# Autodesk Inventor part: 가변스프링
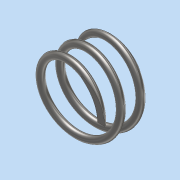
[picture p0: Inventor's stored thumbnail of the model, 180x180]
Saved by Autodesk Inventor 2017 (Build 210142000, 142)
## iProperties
Part Number: 가변스프링
Material: 스테인레스 스틸
Document SubType Name: Modeling
Designer: mrc
Density: 8 g/cm^3
Appearance: 반연마
Mass: 3.52039 g
Surface Area: 9.29262 cm^2
Volume: 0.440049 cm^3
Author: mrc
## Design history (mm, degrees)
sketch "스케치1"
  geometry: L1 (-10, 12.7)-(10, 12.7); L2 (10, 12.7)-(10, 0); L3 (10, 0)-(-10, 0); L4 (-10, 0)-(-10, 12.7); L5 (0, 12.7)-(0, 0); C1 r 1 at (10, 0); 1 further point
  constraints: 10 end point, 2 coincident, 2 midpoint, 2 parallel, 1 centre point, 1 horizontal, 1 perpendicular, 1 vertical
  dimensions: "d0" = 2 diameter of C1; "d1" = 20 distance between parallel lines of L2 L4; "d2" = 12.7 distance between parallel lines of L3 L1 (derived)
feature "코일1" sketch "스케치1" pitch "d3" = 10; turns "d5" = 5; dims "d4" = 28, "d6" = 0, angle "d7" = 90 deg, angle "d8" = 90 deg, "d9" = 0, "d10" = 0
sketch "스케치2"
  geometry: L1 (-15, 12.7)-(15, 12.7); L2 (15, 12.7)-(15, 0); L3 (15, 0)-(-15, 0); L4 (-15, 0)-(-15, 12.7); 2 further points
  constraints: 8 end point, 2 parallel, 1 coincident, 1 horizontal, 1 midpoint, 1 perpendicular
  dimensions: "d12" = 30 distance between parallel lines of L4 L2; "d13" = 12.7 distance between parallel lines of L3 L1 (= d2)
extrude "돌출1" sketch "스케치2" stored distance "d14" = 30; taper "d15" = 0 deg
node "솔리드1"
